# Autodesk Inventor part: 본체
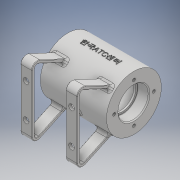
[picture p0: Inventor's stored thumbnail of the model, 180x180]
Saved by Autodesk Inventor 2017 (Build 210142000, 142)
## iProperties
Part Number: 본체
Material: 일반
Document SubType Name: Modeling
Designer: Administrator
Density: 1 g/cm^3
Appearance: 기본값
Author: Administrator
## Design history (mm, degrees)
sketch "스케치2"
  geometry: L1 (0, 16)-(0, 29); L2 (0, 29)-(70, 29); L3 (70, 29)-(70, 16); L4 (70, 16)-(58, 16); L5 (58, 16)-(58, 14); L6 (58, 14)-(56, 14); L7 (56, 14)-(56, 21); L8 (56, 21)-(14, 21); L9 (14, 21)-(14, 14); L10 (14, 14)-(12, 14); L11 (12, 14)-(12, 16); L12 (12, 16)-(0, 16); L13 (0, 0)-(70, 0)
  constraints: 26 end point, 8 perpendicular, 6 point on line, 1 horizontal, 1 vertical
  dimensions: "d1" = 70 distance of L1.end L2.end; "d2" = 42 diameter of L8 L13; "d3" = 12 distance of L11.end L1.start; "d4" = 12 distance of L3.end L4.end; "d5" = 2 distance of L5.end L6.end; "d6" = 42 distance of L7.end L8.end; "d7" = 58 diameter of L2 L13; "d8" = 32 diameter of L12 L13; "d9" = 28 diameter of L10 L13
revolve "회전1" sketch "스케치2" stored, may be unused: angle "d10" = 90 deg
sketch "스케치3"
  geometry: 2 further points
  constraints: 1 vertical alignment
  dimensions: "d11" = 21 distance of point (0, 0) point (0, 21)
hole "구멍1" sketch "스케치3" at (0, 21) diameter "d12" = 3.242; stored, may be unused: countersink angle "d16" = 90 deg, drill point angle "d18" = 118 deg; dims "d13" = 8, "d14" = 4, "d15" = 2, "d17" = 10
sketch "스케치4"
  geometry: C1 r 1.621 at (0, 21) reference; 2 further points
  constraints: 1 coincident, 1 vertical alignment
hole "구멍2" sketch "스케치4" at (0, 21) diameter "d22" = 3.242; stored, may be unused: countersink angle "d26" = 90 deg, drill point angle "d28" = 118 deg; dims "d23" = 8, "d24" = 4, "d25" = 2, "d27" = 10
node "작업 평면1"
sketch "스케치5"
  geometry: C1 r 5 at (-35, 0); 1 further point
  constraints: 1 centre point, 1 horizontal alignment
  dimensions: "d33" = 10 diameter of C1; "d34" = 35 distance of point (0, 0) C1.centre
extrude "돌출1" join sketch "스케치5" stored distance "d35" = 10; taper "d36" = 0 deg
hole "구멍3" diameter "d39" = 5.188; stored, may be unused: countersink angle "d43" = 90 deg, drill point angle "d45" = 118 deg; dims "d37" = 10, "d38" = 10, "d40" = 6, "d41" = 4, "d42" = 2, "d44" = 8
node "작업 평면3"
sketch "스케치6"
  geometry: L1 (17.993, -22.743)-(46.464, -36.02); L2 (55, -30.582)-(55, 30.582); L3 (46.464, 36.02)-(17.993, 22.743); L4 (20.438, 20.574)-(47.732, 33.301); L5 (52, 30.582)-(52, -30.582); L6 (47.732, -33.301)-(20.438, -20.574); C1 r 1.621 at (0, -21) reference; C2 r 1.621 at (21, 0) reference; C3 r 1.621 at (0, 21) reference; C4 r 1.621 at (-21, 0) reference; C5 r 16 at (0, 0) reference; A1 r 29 centre (0, 0) between (17.993, -22.743) and (17.993, 22.743) reference; A2 r 6 centre (49, -30.582) between (46.464, -36.02) and (55, -30.582); A3 r 6 centre (49, 30.582) between (55, 30.582) and (46.464, 36.02); A4 r 3 centre (49, 30.582) between (52, 30.582) and (47.732, 33.301); A5 r 3 centre (49, -30.582) between (47.732, -33.301) and (52, -30.582); 4 further points
  constraints: 12 end point, 12 point on circle, 4 centre point, 4 point on line, 4 tangent, 1 equal radius, 1 horizontal alignment, 1 midpoint, 1 vertical, 2 other
  dimensions: "d48" = 55 distance from line of point (0, 0) L2; "d49" = 65 deg angle of L2 L1; "d50" = 65 deg angle of L2 L3; "d51" = 80 distance of point (55, -40) point (55, 40); "d52" = 6 radius of A2 (derived); "d53" = 3 distance between parallel lines of L2 L5; "d54" = 3 distance between parallel lines of L1 L6; "d55" = 3 distance between parallel lines of L3 L4
extrude "돌출2" join sketch "스케치6" distance "d56" = 12; taper "d57" = 0 deg
node "작업 평면4"
sketch "스케치7"
  geometry: L1 (-17.993, 22.743)-(-46.464, 36.02); L2 (-55, 30.582)-(-55, -30.582); L3 (-46.464, -36.02)-(-17.993, -22.743); L4 (-20.438, -20.574)-(-47.732, -33.301); L5 (-52, -30.582)-(-52, 30.582); L6 (-47.732, 33.301)-(-20.438, 20.574); C1 r 1.621 at (0, -21) reference; C2 r 1.621 at (-21, 0) reference; C3 r 1.621 at (0, 21) reference; C4 r 1.621 at (21, 0) reference; C5 r 16 at (0, 0) reference; A1 r 29 centre (0, 0) between (-17.993, 22.743) and (-17.993, -22.743) reference; A2 r 6 centre (-49, 30.582) between (-46.464, 36.02) and (-55, 30.582); A3 r 6 centre (-49, -30.582) between (-55, -30.582) and (-46.464, -36.02); A4 r 3 centre (-49, -30.582) between (-52, -30.582) and (-47.732, -33.301); A5 r 3 centre (-49, 30.582) between (-47.732, 33.301) and (-52, 30.582); 4 further points
  constraints: 12 end point, 12 point on circle, 4 centre point, 4 point on line, 4 tangent, 1 equal radius, 1 horizontal alignment, 1 midpoint, 1 vertical, 2 other
  dimensions: "d59" = 80 distance of point (-55, 40) point (-55, -40); "d60" = 65 deg angle of L2 L1; "d61" = 65 deg angle of L2 L3; "d62" = 55 distance from line of point (0, 0) L2; "d63" = 6 radius of A2 (derived); "d64" = 3 distance between parallel lines of L2 L5; "d65" = 3 distance between parallel lines of L1 L6; "d66" = 3 distance between parallel lines of L4 L3
extrude "돌출3" join sketch "스케치7" distance "d67" = 12; taper "d68" = 0 deg
sketch "스케치8"
  geometry: L1 (0, 0)-(10.945, -30.07); L2 (0, 0)-(32, 0)
  constraints: 4 end point, 1 equal length, 1 horizontal
  dimensions: "d69" = 32 distance of L1.start L1.end; "d70" = 70 deg angle of L1 L2
node "작업 평면5"
sketch "스케치9"
  geometry: L1 (-17, -12.342)-(-5, -12.342) reference; L2 (-5, -12.342)-(-5, -15.218) reference; L3 (-5, -15.218)-(-17, -15.218) reference; L4 (-17, -15.218)-(-17, -12.342) reference; L5 (-17, 27.526)-(-5, 27.526) reference; L6 (-5, 27.526)-(-5, 26.323) reference; L7 (-5, 26.323)-(-17, 26.323) reference; L8 (-17, 26.323)-(-17, 27.526) reference; L9 (-53, 26.323)-(-65, 26.323) reference; L10 (-65, 26.323)-(-65, 27.526) reference; L11 (-65, 27.526)-(-53, 27.526) reference; L12 (-53, 27.526)-(-53, 26.323) reference; L13 (-53, -15.218)-(-65, -15.218) reference; L14 (-65, -15.218)-(-65, -12.342) reference; L15 (-65, -12.342)-(-53, -12.342) reference; L16 (-53, -12.342)-(-53, -15.218) reference; L17 (-70, -29)-(-70, 29) reference; L18 (0, -29)-(0, 29) reference; C1 r 6 at (-35, 0); 3 further points
  constraints: 2 horizontal alignment, 1 centre point, 1 midpoint, 1 other
  dimensions: "d71" = 12 diameter of C1; "d72" = 35 distance from line of C1.centre L18
extrude "돌출4" join sketch "스케치9" stored distance "d73" = 12; taper "d74" = 0 deg
hole "구멍4" diameter "d77" = 5.188; stored, may be unused: countersink angle "d81" = 90 deg, drill point angle "d83" = 118 deg; dims "d75" = 10, "d76" = 10, "d78" = 6, "d79" = 4, "d80" = 2, "d82" = 15
sketch "스케치10"
  geometry: L1 (-60, 61.164)-(-60, 0) reference; L2 (-60, 0)-(-60, -6) reference; L3 (0, -6)-(0, 0) reference; L4 (0, 61.164)-(0, 67.164) reference; C1 r 3 at (-54, 48.582); C2 r 3 at (-54, 12.582); C3 r 3 at (-6, 12.582); C4 r 3 at (-6, 48.582); 4 further points
  constraints: 4 centre point
  dimensions: "d84" = 6 diameter of C1; "d85" = 6 diameter of C2; "d86" = 6 diameter of C3; "d87" = 6 diameter of C4; "d88" = 36 distance of C2.centre C1.centre; "d89" = 6 distance from line of L1 C1.centre; "d90" = 6 distance from line of L2 C2.centre; "d91" = 6 distance from line of L3 C3.centre; "d92" = 6 distance from line of L4 C4.centre; "d93" = 36 distance of C4.centre C3.centre; "d94" = 18 vertical distance of point (-65, 30.582) C1.centre; "d95" = 18 vertical distance of point (-65, 30.582) C4.centre
extrude "돌출5" cut sketch "스케치10" distance "d96" = 12; taper "d97" = 0 deg
node "작업 평면6"
sketch "스케치11"
  geometry: L1 (0, 29)-(70, 29) reference; 2 further points
  constraints: 1 other
  dimensions: "d99" = 35 distance of point (35, 0) point (0, 0); "d100" = 29 distance from line of point (35, 0) L1
feature "엠보싱1" sketch "스케치11" dims "d1" = 70, "d2" = 42, "d3" = 12, "d4" = 12, "d5" = 2, "d6" = 42, "d7" = 58, "d8" = 32, "d9" = 28, "d101" = 0.5, "d102" = 0
fillet "모깎기1" dims "d103" = 1, "d104" = 0.5, "d105" = 3
fillet "모깎기2" dims "d106" = 3, "d107" = 0.3
chamfer "모따기1" distance "d108" = 1; stored, may be unused: second distance "d109" = 2, angle "d110" = 45 deg
chamfer "모따기2" distance "d111" = 1; stored, may be unused: second distance "d112" = 2, angle "d113" = 45 deg
node "솔리드1"
pattern_circular "원형 패턴1" dims angle "d20" = 360 deg
pattern_circular "원형 패턴2" dims angle "d30" = 360 deg
node "투영된 루프1"
node "절단 모서리 투영1"
node "절단 모서리 투영2"
other parameters: "d32" = 32, "d47" = 5, "d58" = 65, "d98" = 44
